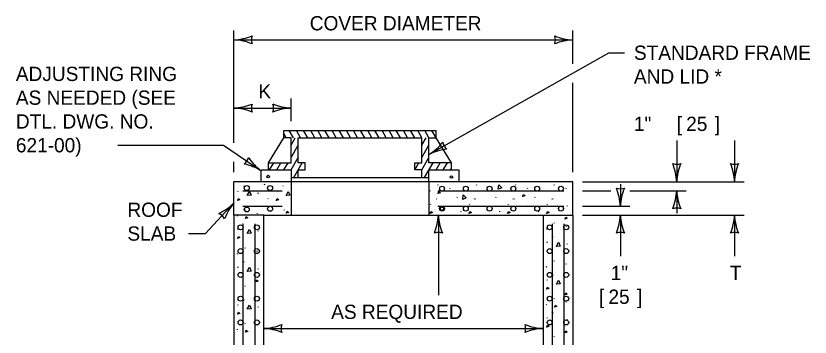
# Model space of a CAD drawing. Extents: x 49991.4 to 50028.3, y 49987.6 to 50011.4.
# Drawn here: x 50024.996 to 50028.336, y 49990.964 to 49992.315 of the extents above; entities that cross this region are included whole.
import ezdxf

# ---------------------------------------------------------------- set-up
doc = ezdxf.new("R2010")
doc.units = 0
for name, color, linetype in [('Level 1', 7, 'Continuous'), ('Level 2', 7, 'Continuous'), ('Level 3', 7, 'Continuous')]:
    doc.layers.add(name, color=color, linetype=linetype)

msp = doc.modelspace()

# ---------------------------------------------------------------- linework, layer by layer
at = {"layer": 'Level 1'}
for p, q in [((50026.1234, 49991.8027), (50026.1234, 49991.8327)), ((50026.1234, 49991.8327), (50026.1534, 49991.8327)), ((50026.1334, 49991.8027), (50026.1234, 49991.82)), ((50026.1634, 49991.8027), (50026.1461, 49991.8327)), ((50026.1534, 49991.8327), (50026.7634, 49991.8327)), ((50026.1934, 49991.8027), (50026.1761, 49991.8327)), ((50026.2234, 49991.8027), (50026.2061, 49991.8327)), ((50026.2534, 49991.8027), (50026.2361, 49991.8327)), ((50026.2834, 49991.8027), (50026.2661, 49991.8327)), ((50026.3134, 49991.8027), (50026.2961, 49991.8327)), ((50026.3434, 49991.8027), (50026.3261, 49991.8327)), ((50026.3734, 49991.8027), (50026.3561, 49991.8327)), ((50026.4034, 49991.8027), (50026.3861, 49991.8327)), ((50026.4334, 49991.8027), (50026.4161, 49991.8327)), ((50026.4634, 49991.8027), (50026.4461, 49991.8327)), ((50026.4934, 49991.8027), (50026.4761, 49991.8327)), ((50026.5234, 49991.8027), (50026.5061, 49991.8327)), ((50026.5534, 49991.8027), (50026.5361, 49991.8327)), ((50026.5834, 49991.8027), (50026.5661, 49991.8327)), ((50026.6134, 49991.8027), (50026.5961, 49991.8327)), ((50026.6434, 49991.8027), (50026.6261, 49991.8327)), ((50026.6734, 49991.8027), (50026.6561, 49991.8327)), ((50026.7034, 49991.8027), (50026.6861, 49991.8327)), ((50026.7334, 49991.8027), (50026.7161, 49991.8327)), ((50026.7634, 49991.8027), (50026.7461, 49991.8327)), ((50026.7634, 49991.8027), (50026.7634, 49991.8327)), ((50026.0584, 49991.6977), (50026.1234, 49991.8027)), ((50026.1534, 49991.8027), (50026.1234, 49991.8027)), ((50026.1534, 49991.6977), (50026.1534, 49991.8027)), ((50026.1534, 49991.7716), (50026.1713, 49991.8027)), ((50026.1534, 49991.7196), (50026.1834, 49991.7716)), ((50026.1834, 49991.6977), (50026.1834, 49991.8027)), ((50026.1834, 49991.8027), (50026.7034, 49991.8027)), ((50026.7034, 49991.6977), (50026.7034, 49991.8027)), ((50026.7034, 49991.7716), (50026.7213, 49991.8027)), ((50026.7034, 49991.7197), (50026.7334, 49991.7716)), ((50026.7334, 49991.6977), (50026.7334, 49991.8027)), ((50026.7334, 49991.8027), (50026.7634, 49991.8027)), ((50026.8284, 49991.6977), (50026.7634, 49991.8027)), ((50026.1534, 49991.6677), (50026.1834, 49991.7196)), ((50026.7034, 49991.6677), (50026.7334, 49991.7196)), ((50026.0584, 49991.6677), (50026.0584, 49991.6977)), ((50026.0584, 49991.6977), (50026.1534, 49991.6977)), ((50026.0634, 49991.6677), (50026.0807, 49991.6977)), ((50026.0934, 49991.6677), (50026.1107, 49991.6977)), ((50026.1234, 49991.6677), (50026.1407, 49991.6977)), ((50026.1646, 49991.6351), (50026.2007, 49991.6977)), ((50026.2134, 49991.6977), (50026.1834, 49991.6977)), ((50026.2134, 49991.6677), (50026.2134, 49991.6977)), ((50026.6734, 49991.6677), (50026.6734, 49991.6977)), ((50026.6734, 49991.6977), (50026.7034, 49991.6977)), ((50026.6734, 49991.6677), (50026.6907, 49991.6977)), ((50026.7146, 49991.6351), (50026.7507, 49991.6977)), ((50026.8284, 49991.6977), (50026.7334, 49991.6977)), ((50026.7634, 49991.6677), (50026.7807, 49991.6977)), ((50026.7934, 49991.6677), (50026.8107, 49991.6977)), ((50026.8234, 49991.6677), (50026.8284, 49991.6763)), ((50026.8284, 49991.6677), (50026.8284, 49991.6977)), ((50026.0284, 49991.6177), (50026.0284, 49991.6677)), ((50026.0284, 49991.6677), (50026.1534, 49991.6677)), ((50026.1534, 49991.6677), (50026.1534, 49991.6177)), ((50026.1834, 49991.6351), (50026.1834, 49991.6677)), ((50026.1834, 49991.6677), (50026.2134, 49991.6677)), ((50026.7034, 49991.6677), (50026.6734, 49991.6677)), ((50026.7034, 49991.6351), (50026.7034, 49991.6677)), ((50026.7334, 49991.6177), (50026.7334, 49991.6677)), ((50026.7334, 49991.6677), (50026.8584, 49991.6677)), ((50026.8584, 49991.6677), (50026.8584, 49991.6177)), ((50025.9134, 49991.4777), (50025.9134, 49991.6177)), ((50027.3384, 49991.6177), (50025.9134, 49991.6177)), ((50026.0415, 49991.6052), (50026.0429, 49991.6082)), ((50026.1534, 49991.6351), (50026.7334, 49991.6351)), ((50026.1534, 49991.6177), (50026.1534, 49991.4777)), ((50026.7334, 49991.6177), (50026.7334, 49991.4777)), ((50026.7705, 49991.6031), (50026.7718, 49991.6061)), ((50026.9337, 49991.6031), (50026.9351, 49991.6061)), ((50027.097, 49991.6031), (50027.0983, 49991.6061)), ((50027.2603, 49991.6031), (50027.2616, 49991.6061)), ((50027.3384, 49991.4777), (50027.3384, 49991.6177)), ((50025.9302, 49991.5766), (50025.9315, 49991.5796)), ((50025.9509, 49991.5801), (50026.1159, 49991.5801)), ((50025.9549, 49991.6005), (50025.9563, 49991.5985)), ((50026.0146, 49991.5689), (50026.0159, 49991.5719)), ((50026.0935, 49991.5766), (50026.0948, 49991.5796)), ((50026.1182, 49991.6005), (50026.1195, 49991.5985)), ((50026.737, 49991.5811), (50026.7373, 49991.5781)), ((50026.7709, 49991.5801), (50027.3009, 49991.5801)), ((50026.8211, 49991.5895), (50026.8225, 49991.5925)), ((50026.9003, 49991.5811), (50026.9006, 49991.5781)), ((50027.0635, 49991.5811), (50027.0639, 49991.5781)), ((50027.1476, 49991.5895), (50027.149, 49991.5925)), ((50027.2268, 49991.5811), (50027.2271, 49991.5781)), ((50027.3109, 49991.5895), (50027.3122, 49991.5925)), ((50026.0562, 49991.5476), (50026.0575, 49991.5456)), ((50026.7648, 49991.5462), (50026.7661, 49991.5442)), ((50026.8514, 49991.5508), (50026.8527, 49991.5538)), ((50026.923, 49991.5469), (50026.9243, 49991.5449)), ((50026.9281, 49991.5462), (50026.9294, 49991.5442)), ((50027.0147, 49991.5508), (50027.016, 49991.5538)), ((50027.0863, 49991.5469), (50027.0876, 49991.5449)), ((50027.0913, 49991.5462), (50027.0927, 49991.5442)), ((50027.1779, 49991.5508), (50027.1793, 49991.5538)), ((50027.2495, 49991.5469), (50027.2509, 49991.5449)), ((50027.2546, 49991.5462), (50027.2559, 49991.5442)), ((50025.9509, 49991.5151), (50026.1159, 49991.5151)), ((50026.7401, 49991.5223), (50026.7414, 49991.5252)), ((50026.7709, 49991.5151), (50027.3009, 49991.5151)), ((50026.8244, 49991.5146), (50026.8258, 49991.5176)), ((50026.9033, 49991.5223), (50026.9047, 49991.5252)), ((50026.9877, 49991.5146), (50026.989, 49991.5176)), ((50027.0666, 49991.5223), (50027.0679, 49991.5252)), ((50027.151, 49991.5146), (50027.1523, 49991.5176)), ((50027.2299, 49991.5223), (50027.2312, 49991.5252)), ((50027.3142, 49991.5146), (50027.3156, 49991.5176)), ((50026.0384, 49991.4777), (50025.9134, 49991.4777)), ((50025.9134, 49991.4777), (50025.9134, 49989.7777)), ((50025.9271, 49991.476), (50025.9275, 49991.473)), ((50025.9606, 49991.498), (50025.9619, 49991.501)), ((50026.0113, 49991.4843), (50026.0126, 49991.4873)), ((50026.1239, 49991.498), (50026.1252, 49991.501)), ((50026.8661, 49991.4933), (50026.8674, 49991.4913)), ((50027.0293, 49991.4933), (50027.0307, 49991.4913)), ((50027.1926, 49991.4933), (50027.1939, 49991.4913)), ((50027.2134, 49991.4777), (50027.3384, 49991.4777)), ((50027.3384, 49991.4777), (50027.3384, 49989.7777)), ((50025.9499, 49991.4418), (50025.9512, 49991.4398)), ((50025.9509, 49991.4401), (50025.9509, 49989.8151)), ((50026.0009, 49991.4401), (50026.0009, 49989.8151)), ((50027.2509, 49991.4401), (50027.2509, 49989.8151)), ((50027.2603, 49991.4437), (50027.2616, 49991.4467)), ((50027.3009, 49991.4401), (50027.3009, 49989.8151)), ((50025.9302, 49991.4171), (50025.9315, 49991.4201)), ((50026.0146, 49991.4095), (50026.0159, 49991.4125)), ((50027.2268, 49991.4216), (50027.2271, 49991.4186)), ((50027.3109, 49991.43), (50027.3122, 49991.433)), ((50027.2495, 49991.3875), (50027.2509, 49991.3855)), ((50027.2546, 49991.3867), (50027.2559, 49991.3847)), ((50025.9606, 49991.3385), (50025.9619, 49991.3415)), ((50027.2299, 49991.3628), (50027.2312, 49991.3658)), ((50027.3142, 49991.3551), (50027.3156, 49991.3581)), ((50025.9271, 49991.3165), (50025.9275, 49991.3135)), ((50026.0113, 49991.3249), (50026.0126, 49991.3279)), ((50025.9499, 49991.2824), (50025.9512, 49991.2804)), ((50025.9549, 49991.2816), (50025.9563, 49991.2796)), ((50027.2603, 49991.2842), (50027.2616, 49991.2872)), ((50027.3109, 49991.2705), (50027.3122, 49991.2735)), ((50025.9302, 49991.2577), (50025.9315, 49991.2607)), ((50026.0146, 49991.25), (50026.0159, 49991.253)), ((50027.2268, 49991.2622), (50027.2271, 49991.2592)), ((50027.2299, 49991.2033), (50027.2312, 49991.2063)), ((50027.2495, 49991.228), (50027.2509, 49991.226)), ((50027.2546, 49991.2273), (50027.2559, 49991.2253)), ((50025.9606, 49991.1791), (50025.9619, 49991.1821)), ((50025.9499, 49991.1229), (50025.9512, 49991.1209)), ((50025.9549, 49991.1221), (50025.9563, 49991.1201)), ((50027.2603, 49991.1247), (50027.2616, 49991.1277)), ((50027.3109, 49991.1111), (50027.3122, 49991.1141)), ((50025.9302, 49991.0982), (50025.9315, 49991.1012)), ((50026.0146, 49991.0906), (50026.0159, 49991.0935)), ((50027.2268, 49991.1027), (50027.2271, 49991.0997)), ((50027.2299, 49991.0439), (50027.2312, 49991.0469)), ((50027.2495, 49991.0685), (50027.2509, 49991.0665)), ((50027.2546, 49991.0678), (50027.2559, 49991.0658)), ((50027.3142, 49991.0362), (50027.3156, 49991.0392)), ((50025.9606, 49991.0196), (50025.9619, 49991.0226)), ((50025.9271, 49990.9976), (50025.9275, 49990.9946)), ((50027.2603, 49990.9653), (50027.2616, 49990.9683))]:
    msp.add_line(p, q, dxfattribs=at)
for points in [[(50027.0249, 49991.586), (50027.0275, 49991.6051), (50027.0395, 49991.5927), (50027.0252, 49991.5861)], [(50025.9696, 49991.5599), (50025.9786, 49991.5769), (50025.9856, 49991.5613), (50025.9699, 49991.5599)], [(50026.1329, 49991.5599), (50026.1419, 49991.5769), (50026.1489, 49991.5613), (50026.1332, 49991.5599)], [(50026.7711, 49991.5681), (50026.7751, 49991.5765), (50026.7818, 49991.5715), (50026.7711, 49991.5681)], [(50025.9279, 49991.5389), (50025.9319, 49991.5473), (50025.9385, 49991.5423), (50025.9279, 49991.5389)], [(50026.0911, 49991.5389), (50026.0951, 49991.5473), (50026.1018, 49991.5423), (50026.0911, 49991.5389)], [(50026.8753, 49991.5433), (50026.8779, 49991.5623), (50026.8898, 49991.55), (50026.8755, 49991.5434)], [(50027.1269, 49991.5555), (50027.1309, 49991.5639), (50027.1376, 49991.5589), (50027.1269, 49991.5555)], [(50025.9613, 49991.463), (50025.9653, 49991.4713), (50025.9719, 49991.4664), (50025.9613, 49991.463)], [(50026.133, 49991.4856), (50026.137, 49991.4939), (50026.1437, 49991.4889), (50026.133, 49991.4856)], [(50026.7377, 49991.4846), (50026.7417, 49991.4929), (50026.7484, 49991.4879), (50026.7377, 49991.4846)], [(50026.901, 49991.4846), (50026.905, 49991.4929), (50026.9117, 49991.4879), (50026.901, 49991.4846)], [(50027.0643, 49991.4846), (50027.0683, 49991.4929), (50027.0749, 49991.4879), (50027.0643, 49991.4846)], [(50027.2275, 49991.4846), (50027.2315, 49991.4929), (50027.2382, 49991.4879), (50027.2275, 49991.4846)], [(50027.3043, 49991.4608), (50027.3083, 49991.4691), (50027.315, 49991.4641), (50027.3043, 49991.4608)], [(50025.9696, 49991.4005), (50025.9786, 49991.4175), (50025.9856, 49991.4018), (50025.9699, 49991.4005)], [(50025.9279, 49991.3795), (50025.9319, 49991.3878), (50025.9385, 49991.3828), (50025.9279, 49991.3795)], [(50027.2693, 49991.3461), (50027.2783, 49991.3631), (50027.2853, 49991.3475), (50027.2696, 49991.3461)], [(50025.9696, 49991.241), (50025.9786, 49991.258), (50025.9856, 49991.2423), (50025.9699, 49991.241)], [(50026.0047, 49991.1963), (50026.0087, 49991.2046), (50026.0153, 49991.1996), (50026.0047, 49991.1963)], [(50027.2693, 49991.1867), (50027.2783, 49991.2037), (50027.2853, 49991.188), (50027.2696, 49991.1867)], [(50027.2275, 49991.1657), (50027.2315, 49991.174), (50027.2382, 49991.169), (50027.2275, 49991.1657)], [(50027.3043, 49991.1419), (50027.3083, 49991.1502), (50027.315, 49991.1452), (50027.3043, 49991.1419)], [(50025.9696, 49991.0816), (50025.9786, 49991.0985), (50025.9856, 49991.0829), (50025.9699, 49991.0816)], [(50027.2609, 49991.0898), (50027.2649, 49991.0981), (50027.2716, 49991.0931), (50027.2609, 49991.0898)], [(50025.9279, 49991.0606), (50025.9319, 49991.0689), (50025.9385, 49991.0639), (50025.9279, 49991.0606)], [(50027.2275, 49991.0063), (50027.2315, 49991.0146), (50027.2382, 49991.0096), (50027.2275, 49991.0063)], [(50025.9613, 49990.9847), (50025.9653, 49990.993), (50025.9719, 49990.988), (50025.9613, 49990.9847)], [(50027.3043, 49990.9825), (50027.3083, 49990.9908), (50027.315, 49990.9858), (50027.3043, 49990.9825)]]:
    msp.add_lwpolyline(points, dxfattribs=at)
msp.add_lwpolyline([(50026.0384, 49991.4777), (50027.2134, 49991.4777), (50027.2134, 49989.4277), (50026.0384, 49989.4277)], close=True, dxfattribs=at)
for centre, radius in [((50026.0572, 49991.6393), 0.00544), ((50026.8281, 49991.6381), 0.00503), ((50025.9671, 49991.5912), 0.0104), ((50026.0652, 49991.5912), 0.0104), ((50026.7884, 49991.5887), 0.0104), ((50026.8884, 49991.5887), 0.0104), ((50026.9884, 49991.5887), 0.0104), ((50027.0884, 49991.5887), 0.0104), ((50027.1884, 49991.5887), 0.0104), ((50027.2884, 49991.5887), 0.0104), ((50025.9671, 49991.501), 0.0104), ((50026.0652, 49991.504), 0.0104), ((50026.7884, 49991.5047), 0.0104), ((50026.7884, 49991.5048), 0.0074), ((50026.8884, 49991.5047), 0.0104), ((50026.9884, 49991.5047), 0.0104), ((50027.0884, 49991.5047), 0.0104), ((50027.1884, 49991.5047), 0.0104), ((50027.2884, 49991.5047), 0.0104), ((50025.9413, 49991.4261), 0.0104), ((50026.01, 49991.4261), 0.0104), ((50027.2409, 49991.4261), 0.0104), ((50027.3105, 49991.4261), 0.0104), ((50025.9413, 49991.3261), 0.0104), ((50026.01, 49991.3261), 0.0104), ((50027.2409, 49991.3261), 0.0104), ((50027.3105, 49991.3261), 0.0104), ((50025.9413, 49991.2261), 0.0104), ((50026.01, 49991.2261), 0.0104), ((50027.2409, 49991.2261), 0.0104), ((50027.3105, 49991.2261), 0.0104), ((50025.9413, 49991.1261), 0.0104), ((50026.01, 49991.1261), 0.0104), ((50027.2409, 49991.1261), 0.0104), ((50027.3105, 49991.1261), 0.0104), ((50025.9413, 49991.0261), 0.0104), ((50026.01, 49991.0261), 0.0104), ((50027.2409, 49991.0261), 0.0104), ((50027.3105, 49991.0261), 0.0104)]:
    msp.add_circle(centre, radius, dxfattribs=at)
at = {"layer": 'Level 3'}
for p, q in [((50025.9134, 49991.7811), (50025.9132, 49992.2541)), ((50027.3383, 49992.1137), (50027.3382, 49992.2541)), ((50025.9132, 49992.2141), (50027.3382, 49992.2141)), ((50026.7334, 49991.732), (50027.4901, 49992.1594)), ((50027.4901, 49992.1594), (50027.5552, 49992.1594)), ((50027.3384, 49991.6577), (50027.3383, 49992.0337)), ((50026.1534, 49991.8725), (50026.1534, 49991.9677)), ((50025.9134, 49991.9277), (50026.1534, 49991.9277)), ((50027.7752, 49991.7911), (50027.7752, 49991.6177)), ((50028.0182, 49991.7911), (50028.0182, 49991.6177)), ((50025.4251, 49991.7712), (50025.8689, 49991.7712)), ((50025.8689, 49991.7712), (50026.0284, 49991.6632)), ((50025.9134, 49991.6577), (50025.9134, 49991.7011)), ((50027.3784, 49991.6177), (50028.0582, 49991.6177)), ((50027.5382, 49991.6081), (50027.5382, 49991.5151)), ((50027.3784, 49991.5801), (50027.4982, 49991.5801)), ((50027.5782, 49991.5801), (50027.8152, 49991.5801)), ((50027.7752, 49991.5801), (50027.7752, 49991.4856)), ((50025.793, 49991.3999), (50025.9134, 49991.5287)), ((50027.3784, 49991.5151), (50027.5782, 49991.5151)), ((50026.773, 49991.4777), (50026.773, 49991.1407)), ((50027.3784, 49991.4777), (50028.0582, 49991.4777)), ((50027.5382, 49991.4777), (50027.5382, 49991.3043)), ((50028.0182, 49991.4777), (50028.0182, 49991.3043)), ((50025.7225, 49991.3999), (50025.793, 49991.3999)), ((50026.0384, 49991.0007), (50027.2134, 49991.0007))]:
    msp.add_line(p, q, dxfattribs=at)
for centre, radius, start, end in [((50025.9018, 49992.4468), 0.233, 272.8273, 292.0772), ((50025.9041, 49991.992), 0.2223, 67.456, 87.6395), ((50026.0415, 49992.2141), 0.0548, 162.1388, 197.8612), ((50027.3474, 49992.4363), 0.2223, 247.456, 267.6395), ((50027.21, 49992.2141), 0.0548, 342.1388, 17.8612), ((50027.3497, 49991.9814), 0.233, 92.8273, 112.0772), ((50025.9019, 49992.1604), 0.233, 272.8273, 292.0772), ((50026.0416, 49991.9277), 0.0548, 162.1388, 197.8612), ((50026.1625, 49992.1499), 0.2223, 247.456, 267.6395), ((50026.0252, 49991.9277), 0.0548, 342.1388, 17.8612), ((50025.9042, 49991.7056), 0.2223, 67.456, 87.6395), ((50026.1649, 49991.695), 0.233, 92.8273, 112.0772), ((50026.6089, 49991.929), 0.233, 302.2857, 321.5355), ((50026.845, 49991.795), 0.0548, 191.5972, 227.3196), ((50026.8347, 49991.5341), 0.2223, 96.9144, 117.0979), ((50025.9222, 49991.7351), 0.0548, 308.0383, 343.7607), ((50026.1605, 49991.842), 0.2223, 213.3555, 233.539), ((50025.9074, 49991.4641), 0.233, 58.7268, 77.9767), ((50027.7752, 49991.7459), 0.0548, 252.1388, 287.8612), ((50027.5425, 49991.6062), 0.233, 2.8273, 22.0772), ((50027.9973, 49991.6086), 0.2223, 157.456, 177.6395), ((50028.0182, 49991.7459), 0.0548, 252.1388, 287.8612), ((50027.7855, 49991.6062), 0.233, 2.8273, 22.0772), ((50028.2403, 49991.6086), 0.2223, 157.456, 177.6395), ((50027.5382, 49991.6433), 0.0548, 252.1388, 287.8612), ((50027.3055, 49991.5036), 0.233, 2.8273, 22.0772), ((50027.7603, 49991.506), 0.2223, 157.456, 177.6395), ((50027.5531, 49991.5893), 0.2223, 337.456, 357.6395), ((50028.0079, 49991.5916), 0.233, 182.8273, 202.0772), ((50025.7574, 49991.6871), 0.2223, 294.3866, 314.5701), ((50026.0912, 49991.3782), 0.233, 139.7579, 159.0077), ((50027.7752, 49991.4519), 0.0548, 72.1388, 107.8612), ((50025.8258, 49991.4351), 0.0548, 29.0694, 64.7918), ((50026.5509, 49991.4869), 0.2223, 337.456, 357.6395), ((50027.0057, 49991.4892), 0.233, 182.8273, 202.0772), ((50027.3161, 49991.4869), 0.2223, 337.456, 357.6395), ((50027.7709, 49991.4892), 0.233, 182.8273, 202.0772), ((50027.7961, 49991.4869), 0.2223, 337.456, 357.6395), ((50028.2509, 49991.4892), 0.233, 182.8273, 202.0772), ((50026.773, 49991.3495), 0.0548, 72.1388, 107.8612), ((50027.5382, 49991.3495), 0.0548, 72.1388, 107.8612), ((50028.0182, 49991.3495), 0.0548, 72.1388, 107.8612), ((50026.0269, 49991.2334), 0.233, 272.8273, 292.0772), ((50026.1666, 49991.0007), 0.0548, 162.1388, 197.8612), ((50027.2225, 49991.2229), 0.2223, 247.456, 267.6395), ((50027.0852, 49991.0007), 0.0548, 342.1388, 17.8612), ((50026.0292, 49990.7786), 0.2223, 67.456, 87.6395), ((50027.2249, 49990.768), 0.233, 92.8273, 112.0772)]:
    msp.add_arc(centre, radius, start, end, dxfattribs=at)

# ---------------------------------------------------------------- texts
at = {"layer": 'Level 2'}
for s, p in [('COVER DIAMETER', (50026.2321, 49992.2541)), ('STANDARD FRAME', (50027.5952, 49992.1302)), ('ADJUSTING RING', (50024.9962, 49992.0412)), ('AND LID *', (50027.5952, 49992.0302)), ('K', (50026.0164, 49991.9677)), ('AS NEEDED (SEE', (50024.9962, 49991.9412)), ('DTL. DWG. NO.', (50024.9962, 49991.8412)), ('1" ', (50027.5952, 49991.8311)), ('[', (50027.7752, 49991.8311)), ('25', (50027.8149, 49991.8311)), (']', (50027.9349, 49991.8311)), ('621-00)', (50024.9962, 49991.7412)), ('ROOF', (50025.4652, 49991.4699)), ('SLAB', (50025.4652, 49991.3699)), ('1"', (50027.4976, 49991.2043)), ('T', (50027.9986, 49991.2043)), ('[', (50027.4484, 49991.1043)), ('25', (50027.4881, 49991.1043)), (']', (50027.6081, 49991.1043)), ('AS REQUIRED', (50026.3221, 49991.0407))]:
    msp.add_text(s, height=0.06, dxfattribs=at).set_placement(p)

doc.saveas('drawing.dxf')
